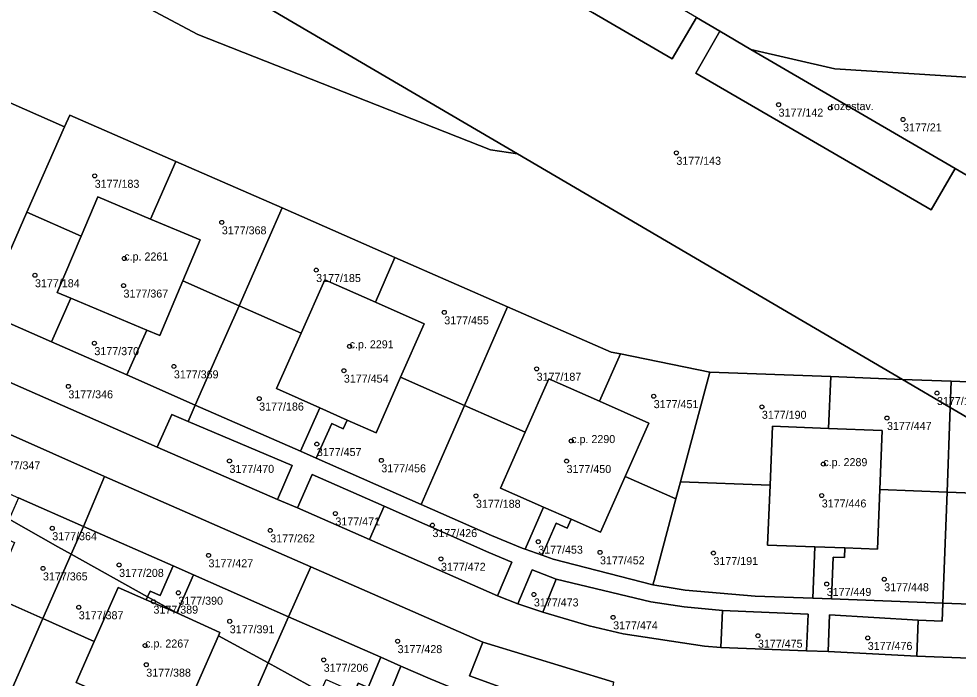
# Model space of a CAD drawing. Extents: x -878211 to -870363, y -1058464 to -1052522.
# Drawn here: x -874043.9 to -873926.5, y -1057031.9 to -1056949.6 of the extents above; entities that cross this region are included whole.
import ezdxf

# ---------------------------------------------------------------- set-up
doc = ezdxf.new("R2010")
doc.units = 0
for name, color, linetype in [('Definiční body', 7, 'Continuous'), ('Polygon budovy', 7, 'Continuous'), ('Polygon parcely', 7, 'Continuous')]:
    doc.layers.add(name, color=color, linetype=linetype)

msp = doc.modelspace()

# ---------------------------------------------------------------- linework, layer by layer
at = {"layer": 'Definiční body'}
for centre in [(-873948.95, -1056960.29994), (-873942.48, -1056960.72994), (-873933.4, -1056962.14994), (-873961.72, -1056966.31994), (-874034.39, -1056969.18994), (-874018.51, -1056974.99994), (-874030.7, -1056979.50994), (-874041.85, -1056981.60994), (-874006.72, -1056980.95994), (-874030.79, -1056982.89994), (-873990.72, -1056986.23994), (-874034.43, -1056990.08994), (-874002.54, -1056990.47994), (-874024.5, -1056992.98994), (-873979.18, -1056993.28994), (-874003.26, -1056993.51994), (-874037.68, -1056995.47994), (-873964.55, -1056996.70994), (-873929.16, -1056996.31994), (-874013.84, -1056997.00994), (-873951.04, -1056998.03994), (-873935.41, -1056999.42994), (-874006.64, -1057002.68994), (-873974.86, -1057002.30994), (-874017.55, -1057004.78994), (-873998.58, -1057004.71994), (-873975.44, -1057004.80994), (-873943.36, -1057005.18994), (-873986.76, -1057009.14994), (-873943.56, -1057009.10994), (-874004.32, -1057011.35994), (-874039.69, -1057013.19994), (-873992.19, -1057012.80994), (-874012.46, -1057013.46994), (-873978.98, -1057014.87994), (-874020.17, -1057016.57994), (-873971.26, -1057016.20994), (-873957.09, -1057016.29994), (-874031.34, -1057017.77994), (-873991.13, -1057017.01994), (-874040.85, -1057018.21994), (-873942.94, -1057020.15994), (-873935.75, -1057019.56994), (-874023.94, -1057021.25994), (-873979.52, -1057021.46994), (-874027.05, -1057022.36994), (-874036.38, -1057023.06994), (-874017.52, -1057024.81994), (-873969.62, -1057024.32994), (-873996.55, -1057027.29994), (-873951.53, -1057026.61994), (-873937.81, -1057026.89994), (-874028.09, -1057027.83994), (-874005.78, -1057029.62994), (-874027.95, -1057030.23994)]:
    msp.add_circle(centre, 0.25, dxfattribs=at)
at = {"layer": 'Polygon budovy'}
for points in [[(-873988.6, -1056932.27), (-873991.63, -1056937.46), (-873972.19, -1056948.79), (-873962.24, -1056954.58), (-873959.22, -1056949.41)], [(-873956.29, -1056951.12), (-873959.28, -1056956.35), (-873929.9, -1056973.44), (-873926.9, -1056968.27), (-873952.41, -1056953.39)], [(-874023.39, -1056982.31), (-874021.23, -1056977.19), (-874027.4, -1056974.59), (-874034.02, -1056971.81), (-874036.09, -1056976.71), (-874039.07, -1056983.74), (-874037.38, -1056984.45), (-874027.89, -1056988.46), (-874026.27, -1056989.14)], [(-874006.27, -1056998.15), (-874002.85, -1056999.68), (-873999.24, -1057001.29), (-873996.17, -1056994.33), (-873993.22, -1056987.65), (-873999.33, -1056984.95), (-874005.63, -1056982.16), (-874008.6, -1056988.84), (-874011.66, -1056995.75)], [(-873980.61, -1057001.2), (-873983.7, -1057008.18), (-873978.3, -1057010.56), (-873974.87, -1057012.08), (-873971.19, -1057013.7), (-873968.1, -1057006.72), (-873965.15, -1057000.06), (-873971.31, -1056997.33), (-873977.66, -1056994.52)], [(-873950.01, -1057007.82), (-873950.32, -1057015.3), (-873944.42, -1057015.52), (-873940.68, -1057015.66), (-873936.59, -1057015.81), (-873936.3, -1057008.35), (-873936.01, -1057000.99), (-873942.7, -1057000.72), (-873949.71, -1057000.44)], [(-874030.34, -1057035.26), (-874023.98, -1057038.07), (-874021.72, -1057032.94), (-874018.93, -1057026.61), (-874018.75, -1057026.21), (-874024.13, -1057023.77), (-874027.95, -1057022.15), (-874031.47, -1057020.59), (-874034.44, -1057027.32), (-874036.71, -1057032.45)]]:
    msp.add_lwpolyline(points, close=True, dxfattribs=at)
at = {"layer": 'Polygon parcely'}
for points in [[(-874156.66, -1056907.49), (-874136.75, -1056919.68), (-874118.33, -1056927.78), (-874098.29, -1056936.6), (-874078.24, -1056945.42), (-874058.2, -1056954.24), (-874038.15, -1056963.06), (-874037.51, -1056961.6), (-874024.26, -1056967.4), (-874010.99, -1056973.2), (-873996.88, -1056979.37), (-873982.81, -1056985.53), (-873969.85, -1056991.2), (-873968.72, -1056991.43), (-873957.55, -1056993.69), (-873942.44, -1056994.26), (-873933.49, -1056994.6), (-873981.56, -1056966.45), (-873984.94, -1056965.93), (-874021.49, -1056951.53), (-874060.01, -1056931.07), (-874140.36, -1056880.4), (-874129.69, -1056863.48), (-874203.06, -1056813.57)], [(-874020.56, -1056943.6), (-873981.56, -1056966.45), (-873933.49, -1056994.6), (-873927.38, -1056994.84), (-873915.37, -1056995.29), (-873915.35, -1056991.97), (-873915.9, -1056983.41), (-873916.29, -1056977.27), (-873917.86, -1056977.34), (-873917.89, -1056976.17), (-873917.9, -1056975.65), (-873916.41, -1056975.58), (-873916.49, -1056974.34), (-873926.9, -1056968.27), (-873929.9, -1056973.44), (-873959.28, -1056956.35), (-873956.29, -1056951.12), (-873959.22, -1056949.41), (-873962.24, -1056954.58), (-873972.19, -1056948.79)], [(-873959.22, -1056949.41), (-873956.29, -1056951.12), (-873952.41, -1056953.39), (-873941.94, -1056955.82), (-873918.81, -1056957.3), (-873917.62, -1056957.07), (-873918.11, -1056948.85)], [(-873901.53, -1057042.32), (-873905.48, -1057030.17), (-873931.69, -1057029.19), (-873942.74, -1057028.59), (-873945.48, -1057028.49), (-873956.17, -1057028.07), (-873958.19, -1057027.94), (-873968.37, -1057026.39), (-873972.63, -1057025.4), (-873978.42, -1057023.69), (-873981.53, -1057022.62), (-873984.06, -1057021.65), (-874000.05, -1057014.61), (-874009.04, -1057010.65), (-874011.57, -1057009.6), (-874026.57, -1057003.09), (-874050.28, -1056992.66)], [(-874058.64, -1056995.39), (-874033.17, -1057006.75), (-874007.37, -1057018.02), (-873985.92, -1057027.43), (-873969.54, -1057032.43)]]:
    msp.add_lwpolyline(points, dxfattribs=at)
for points in [[(-874129.69, -1056863.48), (-874140.36, -1056880.4), (-874060.01, -1056931.07), (-874021.49, -1056951.53), (-873984.94, -1056965.93), (-873981.56, -1056966.45), (-874020.56, -1056943.6), (-874014.23, -1056932.75), (-874049.34, -1056914.15), (-874056.93, -1056909.47), (-874073.45, -1056899.05), (-874078.93, -1056895.35), (-874102.53, -1056878.64), (-874108.33, -1056874.46)], [(-873988.6, -1056932.27), (-873991.63, -1056937.46), (-873972.19, -1056948.79), (-873962.24, -1056954.58), (-873959.22, -1056949.41)], [(-873956.29, -1056951.12), (-873959.28, -1056956.35), (-873929.9, -1056973.44), (-873926.9, -1056968.27), (-873952.41, -1056953.39)], [(-874038.15, -1056963.06), (-874058.2, -1056954.24), (-874070.3, -1056981.67), (-874056.11, -1056987.91), (-874054.21, -1056988.34), (-874052.28, -1056988), (-874048.51, -1056986.53), (-874048.34, -1056986.15), (-874044.68, -1056977.84), (-874042.86, -1056973.72)], [(-873916.49, -1056974.34), (-873917.62, -1056957.07), (-873918.81, -1056957.3), (-873941.94, -1056955.82), (-873952.41, -1056953.39), (-873926.9, -1056968.27)], [(-874024.26, -1056967.4), (-874037.51, -1056961.6), (-874038.15, -1056963.06), (-874042.86, -1056973.72), (-874036.09, -1056976.71), (-874034.02, -1056971.81), (-874027.4, -1056974.59)], [(-874016.36, -1056985.42), (-874010.99, -1056973.2), (-874024.26, -1056967.4), (-874027.4, -1056974.59), (-874021.23, -1056977.19), (-874023.39, -1056982.31)], [(-874027.89, -1056988.46), (-874026.27, -1056989.14), (-874023.39, -1056982.31), (-874021.23, -1056977.19), (-874027.4, -1056974.59), (-874034.02, -1056971.81), (-874036.09, -1056976.71), (-874039.07, -1056983.74), (-874037.38, -1056984.45)], [(-874016.36, -1056985.42), (-874008.6, -1056988.84), (-874005.63, -1056982.16), (-873999.33, -1056984.95), (-873996.88, -1056979.37), (-874010.99, -1056973.2)], [(-874039.79, -1056989.91), (-874037.38, -1056984.45), (-874039.07, -1056983.74), (-874036.09, -1056976.71), (-874042.86, -1056973.72), (-874044.68, -1056977.84), (-874048.34, -1056986.15), (-874047.56, -1056986.49)], [(-873988.2, -1056997.85), (-873982.81, -1056985.53), (-873996.88, -1056979.37), (-873999.33, -1056984.95), (-873993.22, -1056987.65), (-873996.17, -1056994.33)], [(-874023.39, -1056982.31), (-874026.27, -1056989.14), (-874027.89, -1056988.46), (-874030.37, -1056994.05), (-874021.82, -1056997.81), (-874019.24, -1056991.96), (-874016.36, -1056985.42)], [(-874002.85, -1056999.68), (-873999.24, -1057001.29), (-873996.17, -1056994.33), (-873993.22, -1056987.65), (-873999.33, -1056984.95), (-874005.63, -1056982.16), (-874008.6, -1056988.84), (-874011.66, -1056995.75), (-874006.27, -1056998.15)], [(-874037.38, -1056984.45), (-874039.79, -1056989.91), (-874030.37, -1056994.05), (-874027.89, -1056988.46)], [(-874019.24, -1056991.96), (-874021.82, -1056997.81), (-874008.69, -1057003.58), (-874006.27, -1056998.15), (-874011.66, -1056995.75), (-874008.6, -1056988.84), (-874016.36, -1056985.42)], [(-873968.72, -1056991.43), (-873969.85, -1056991.2), (-873982.81, -1056985.53), (-873988.2, -1056997.85), (-873980.61, -1057001.2), (-873977.66, -1056994.52), (-873971.31, -1056997.33)], [(-874021.82, -1056997.81), (-874030.37, -1056994.05), (-874039.79, -1056989.91), (-874047.56, -1056986.49), (-874050.28, -1056992.66), (-874026.57, -1057003.09), (-874024.76, -1056998.98), (-874022.73, -1056999.87)], [(-873961.78, -1057009.51), (-873961.21, -1057007.38), (-873957.55, -1056993.69), (-873968.72, -1056991.43), (-873971.31, -1056997.33), (-873965.15, -1057000.06), (-873968.1, -1057006.72)], [(-874006.71, -1057004.46), (-873993.61, -1057010.22), (-873991.87, -1057006.24), (-873988.2, -1056997.85), (-873996.17, -1056994.33), (-873999.24, -1057001.29), (-874002.85, -1056999.68), (-874003.34, -1057000.78), (-874004.78, -1057000.13)], [(-873961.21, -1057007.38), (-873950.01, -1057007.82), (-873949.71, -1057000.44), (-873942.7, -1057000.72), (-873942.44, -1056994.26), (-873957.55, -1056993.69)], [(-873936.01, -1057000.99), (-873936.3, -1057008.35), (-873927.9, -1057008.67), (-873927.5, -1056998.11), (-873933.49, -1056994.6), (-873942.44, -1056994.26), (-873942.7, -1057000.72)], [(-874035.8, -1057012.98), (-874033.17, -1057006.75), (-874058.64, -1056995.39), (-874059.3, -1056996.89), (-874060.58, -1056999.78), (-874052.49, -1057003.33), (-874049.14, -1057004.8), (-874049.98, -1057006.73), (-874043.9, -1057009.41)], [(-873968.1, -1057006.72), (-873965.15, -1057000.06), (-873971.31, -1056997.33), (-873977.66, -1056994.52), (-873980.61, -1057001.2), (-873983.7, -1057008.18), (-873978.3, -1057010.56), (-873974.87, -1057012.08), (-873971.19, -1057013.7)], [(-873933.49, -1056994.6), (-873927.5, -1056998.11), (-873927.38, -1056994.84)], [(-873913.75, -1056995.35), (-873915.37, -1056995.29), (-873927.38, -1056994.84), (-873927.5, -1056998.11), (-873918.38, -1057003.46), (-873914.07, -1057003.63)], [(-873978.49, -1057016.57), (-873980.62, -1057015.81), (-873981, -1057015.67), (-873984.83, -1057014.09), (-873993.61, -1057010.22), (-874006.71, -1057004.46), (-874008.69, -1057003.58), (-874021.82, -1056997.81), (-874022.73, -1056999.87), (-874009.7, -1057005.38), (-874011.57, -1057009.6), (-874009.04, -1057010.65), (-874007.23, -1057006.48), (-873998.23, -1057010.45), (-873985.15, -1057016.22), (-873982.28, -1057017.44), (-873984.06, -1057021.65), (-873981.53, -1057022.62), (-873979.74, -1057018.38), (-873976.72, -1057019.57), (-873964.93, -1057022.38), (-873960.76, -1057023.01), (-873955.95, -1057023.48), (-873945.27, -1057023.92), (-873945.48, -1057028.49), (-873942.74, -1057028.59), (-873942.57, -1057023.99), (-873931.52, -1057024.68), (-873928.5, -1057024.79), (-873928.42, -1057022.55), (-873942.33, -1057022.03), (-873944.67, -1057021.94), (-873951.87, -1057021.67), (-873960.62, -1057020.92), (-873962.64, -1057020.59), (-873964.65, -1057020.27), (-873977.1, -1057017.07)], [(-873978.3, -1057010.56), (-873983.7, -1057008.18), (-873980.61, -1057001.2), (-873988.2, -1056997.85), (-873991.87, -1057006.24), (-873993.61, -1057010.22), (-873984.83, -1057014.09), (-873981, -1057015.67), (-873980.62, -1057015.81)], [(-874026.57, -1057003.09), (-874011.57, -1057009.6), (-874009.7, -1057005.38), (-874022.73, -1056999.87), (-874024.76, -1056998.98)], [(-874006.27, -1056998.15), (-874008.69, -1057003.58), (-874006.71, -1057004.46), (-874004.78, -1057000.13), (-874003.34, -1057000.78), (-874002.85, -1056999.68)], [(-873927.9, -1057008.67), (-873921.23, -1057008.93), (-873921, -1057003.35), (-873918.38, -1057003.46), (-873927.5, -1056998.11)], [(-873940.68, -1057015.66), (-873936.59, -1057015.81), (-873936.3, -1057008.35), (-873936.01, -1057000.99), (-873942.7, -1057000.72), (-873949.71, -1057000.44), (-873950.01, -1057007.82), (-873950.32, -1057015.3), (-873944.42, -1057015.52)], [(-874010.17, -1057024.24), (-874007.37, -1057018.02), (-874033.17, -1057006.75), (-874035.8, -1057012.98), (-874024.6, -1057017.9), (-874022.03, -1057019.03)], [(-874000.05, -1057014.61), (-873998.23, -1057010.45), (-874007.23, -1057006.48), (-874009.04, -1057010.65)], [(-873976.73, -1057012.57), (-873978.49, -1057016.57), (-873977.1, -1057017.07), (-873964.65, -1057020.27), (-873964.51, -1057019.74), (-873961.78, -1057009.51), (-873968.1, -1057006.72), (-873971.19, -1057013.7), (-873974.87, -1057012.08), (-873975.36, -1057013.17)], [(-873964.51, -1057019.74), (-873964.65, -1057020.27), (-873962.64, -1057020.59), (-873960.62, -1057020.92), (-873951.87, -1057021.67), (-873944.67, -1057021.94), (-873944.42, -1057015.52), (-873950.32, -1057015.3), (-873950.01, -1057007.82), (-873961.21, -1057007.38), (-873961.78, -1057009.51)], [(-873940.68, -1057015.66), (-873940.72, -1057016.86), (-873942.14, -1057016.8), (-873942.33, -1057022.03), (-873928.42, -1057022.55), (-873927.9, -1057008.67), (-873936.3, -1057008.35), (-873936.59, -1057015.81)], [(-874038.98, -1057015.53), (-874037.33, -1057016.45), (-874035.8, -1057012.98), (-874043.9, -1057009.41), (-874045.06, -1057012.06)], [(-873928.42, -1057022.55), (-873915.9, -1057023.02), (-873915.62, -1057016.53), (-873921.53, -1057016.28), (-873921.23, -1057008.93), (-873927.9, -1057008.67)], [(-874000.05, -1057014.61), (-873984.06, -1057021.65), (-873982.28, -1057017.44), (-873985.15, -1057016.22), (-873998.23, -1057010.45)], [(-873978.3, -1057010.56), (-873980.62, -1057015.81), (-873978.49, -1057016.57), (-873976.73, -1057012.57), (-873975.36, -1057013.17), (-873974.87, -1057012.08)], [(-874040.88, -1057024.48), (-874037.33, -1057016.45), (-874038.98, -1057015.53), (-874045.06, -1057012.06), (-874046.03, -1057014.25), (-874044.39, -1057014.96), (-874047.29, -1057021.65)], [(-874024.6, -1057017.9), (-874035.8, -1057012.98), (-874037.33, -1057016.45), (-874027.78, -1057021.76), (-874027.46, -1057021.05), (-874026.23, -1057021.59)], [(-874027.95, -1057022.15), (-874027.78, -1057021.76), (-874037.33, -1057016.45), (-874040.88, -1057024.48), (-874034.44, -1057027.32), (-874031.47, -1057020.59)], [(-873944.42, -1057015.52), (-873944.67, -1057021.94), (-873942.33, -1057022.03), (-873942.14, -1057016.8), (-873940.72, -1057016.86), (-873940.68, -1057015.66)], [(-874022.03, -1057019.03), (-874024.6, -1057017.9), (-874026.23, -1057021.59), (-874027.46, -1057021.05), (-874027.78, -1057021.76), (-874026.42, -1057022.51), (-874024.13, -1057023.77)], [(-873985.92, -1057027.43), (-874007.37, -1057018.02), (-874010.17, -1057024.24), (-873998.64, -1057029.31), (-873996.13, -1057030.42), (-873992.49, -1057032.02), (-873988.16, -1057033.81), (-873983.57, -1057035.48), (-873982.84, -1057033.33), (-873987.56, -1057031.63)], [(-873978.42, -1057023.69), (-873976.72, -1057019.57), (-873979.74, -1057018.38), (-873981.53, -1057022.62)], [(-874010.17, -1057024.24), (-874022.03, -1057019.03), (-874024.13, -1057023.77), (-874018.75, -1057026.21), (-874018.93, -1057026.61), (-874012.72, -1057030.01)], [(-873956.17, -1057028.07), (-873955.95, -1057023.48), (-873960.76, -1057023.01), (-873964.93, -1057022.38), (-873976.72, -1057019.57), (-873978.42, -1057023.69), (-873972.63, -1057025.4), (-873968.37, -1057026.39), (-873958.19, -1057027.94)], [(-874021.72, -1057032.94), (-874018.93, -1057026.61), (-874018.75, -1057026.21), (-874024.13, -1057023.77), (-874027.95, -1057022.15), (-874031.47, -1057020.59), (-874034.44, -1057027.32), (-874036.71, -1057032.45), (-874030.34, -1057035.26), (-874023.98, -1057038.07)], [(-874051.01, -1057036.01), (-874046.79, -1057037.88), (-874040.88, -1057024.48), (-874047.29, -1057021.65), (-874049.54, -1057026.83), (-874055.98, -1057024.03), (-874059.59, -1057032.22)], [(-874026.42, -1057022.51), (-874027.78, -1057021.76), (-874027.95, -1057022.15), (-874024.13, -1057023.77)], [(-873956.17, -1057028.07), (-873945.48, -1057028.49), (-873945.27, -1057023.92), (-873955.95, -1057023.48)], [(-873928.42, -1057022.55), (-873928.5, -1057024.79), (-873931.52, -1057024.68), (-873931.69, -1057029.19), (-873905.48, -1057030.17), (-873907.71, -1057023.32), (-873913.07, -1057023.12), (-873915.9, -1057023.02)], [(-874033.98, -1057043.53), (-874030.34, -1057035.26), (-874036.71, -1057032.45), (-874034.44, -1057027.32), (-874040.88, -1057024.48), (-874046.79, -1057037.88), (-874037.64, -1057041.92)], [(-873998.64, -1057029.31), (-874010.17, -1057024.24), (-874012.72, -1057030.01), (-874006.66, -1057033.33), (-874006.13, -1057033.6), (-874005.47, -1057032.1), (-874001.95, -1057033.65), (-874001.46, -1057032.56), (-874000.23, -1057033.1)], [(-873942.74, -1057028.59), (-873931.69, -1057029.19), (-873931.52, -1057024.68), (-873942.57, -1057023.99)], [(-874012.72, -1057030.01), (-874018.93, -1057026.61), (-874021.72, -1057032.94), (-874015.27, -1057035.79)], [(-873969.54, -1057032.43), (-873985.92, -1057027.43), (-873987.56, -1057031.63), (-873982.84, -1057033.33), (-873970.35, -1057037)], [(-873996.13, -1057030.42), (-873998.64, -1057029.31), (-874000.23, -1057033.1), (-874001.46, -1057032.56), (-874001.95, -1057033.65), (-873998.15, -1057035.33)], [(-874006.13, -1057033.6), (-874006.66, -1057033.33), (-874012.72, -1057030.01), (-874015.27, -1057035.79), (-874008.43, -1057038.8)], [(-873996.13, -1057030.42), (-873998.15, -1057035.33), (-873992.74, -1057037.72), (-873993.75, -1057040.01), (-873992.71, -1057040.55), (-873987.08, -1057043.43), (-873983.57, -1057035.48), (-873988.16, -1057033.81), (-873992.49, -1057032.02)]]:
    msp.add_lwpolyline(points, close=True, dxfattribs=at)

# ---------------------------------------------------------------- texts
at = {"layer": 'Definiční body'}
for s, p in [('rozestav.', (-873942.48, -1056960.98)), ('3177/142', (-873948.95, -1056961.789)), ('3177/21', (-873933.4, -1056963.639)), ('3177/143', (-873961.72, -1056967.809)), ('3177/183', (-874034.39, -1056970.679)), ('3177/368', (-874018.51, -1056976.489)), ('c.p. 2261', (-874030.7, -1056979.76)), ('3177/185', (-874006.72, -1056982.449)), ('3177/184', (-874041.85, -1056983.099)), ('3177/367', (-874030.79, -1056984.389)), ('3177/455', (-873990.72, -1056987.729)), ('3177/370', (-874034.43, -1056991.579)), ('c.p. 2291', (-874002.54, -1056990.73)), ('3177/369', (-874024.5, -1056994.479)), ('3177/454', (-874003.26, -1056995.009)), ('3177/187', (-873979.18, -1056994.779)), ('3177/346', (-874037.68, -1056996.969)), ('3177/186', (-874013.84, -1056998.499)), ('3177/451', (-873964.55, -1056998.199)), ('3177/189', (-873929.16, -1056997.809)), ('3177/190', (-873951.04, -1056999.529)), ('3177/447', (-873935.41, -1057000.919)), ('c.p. 2290', (-873974.86, -1057002.56)), ('3177/457', (-874006.64, -1057004.179)), ('3177/347', (-874046.76, -1057005.839)), ('c.p. 2289', (-873943.36, -1057005.44)), ('3177/470', (-874017.55, -1057006.279)), ('3177/456', (-873998.58, -1057006.209)), ('3177/450', (-873975.44, -1057006.299)), ('3177/188', (-873986.76, -1057010.639)), ('3177/446', (-873943.56, -1057010.599)), ('3177/471', (-874004.32, -1057012.849)), ('3177/364', (-874039.69, -1057014.689)), ('3177/262', (-874012.46, -1057014.959)), ('3177/426', (-873992.19, -1057014.299)), ('3177/453', (-873978.98, -1057016.369)), ('3177/452', (-873971.26, -1057017.699)), ('3177/427', (-874020.17, -1057018.069)), ('3177/472', (-873991.13, -1057018.509)), ('3177/191', (-873957.09, -1057017.789)), ('3177/365', (-874040.85, -1057019.709)), ('3177/208', (-874031.34, -1057019.269)), ('3177/448', (-873935.75, -1057021.059)), ('3177/449', (-873942.94, -1057021.649)), ('3177/390', (-874023.94, -1057022.749)), ('3177/473', (-873979.52, -1057022.959)), ('3177/387', (-874036.38, -1057024.559)), ('3177/389', (-874027.05, -1057023.859)), ('3177/474', (-873969.62, -1057025.819)), ('3177/391', (-874017.52, -1057026.309)), ('c.p. 2267', (-874028.09, -1057028.09)), ('3177/475', (-873951.53, -1057028.109)), ('3177/428', (-873996.55, -1057028.789)), ('3177/476', (-873937.81, -1057028.389)), ('3177/388', (-874027.95, -1057031.729)), ('3177/206', (-874005.78, -1057031.119))]:
    msp.add_text(s, height=0.999996, dxfattribs=at).set_placement(p)

doc.saveas('drawing.dxf')
